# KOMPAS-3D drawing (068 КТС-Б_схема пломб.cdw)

Referenced files: Graphic.tdp
Referenced files in D:\100_Работа\003_КД\003_Проекты\СхемыУстПриборов\: КТС-Б_Труба_Ду100.cdw
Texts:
  ПСПД-0000-2015
  Узел учёта тепловой энергии и теплоносителя
  Кремляков А.И.
  Служба проектно-сметная
  ПромСервисА.И.
  Лит-Масса-Масштаб
  Материал-Предприятие
  Title Specification
  Body Specification ( left align )
  Body Specificaton ( centered )
  ГОСТ 16037-80-У20-ЗН- 3
  пломба
  *Размеры для справок.
  Допустимое   угловое  смещение   деталей поз.1, 2, 3
  относительно фланцев и номинального положения  2 .
  Сварные швы проверить внешним осмотром по ГОСТ 3242-79.
  Трещины, прожоги, свищи, раковины, непровары не допускаются.
  Измерительный участок испытать на прочность и
  герметичность пробным гидравлическим давлением Pпр=2,0 МПа в
  течение 30 мин. Течь, потение, видимые остаточные деформации не
  допускаются.
  Термометр сопротивления поз.1 и выступающие части бобышки
  поз.2 и гильзы поз.3 изолировать на высоту 50...60 мм трубчатой
  теплоизоляцией  1/2"; S=13 мм, закрепив её лентой самоклеещей.
  ООО "ПОИНТ"
  Tермометр
  сопротивления
  платиновый КТС-Б
  Pt100
  Tермометр  сопротивления  платиновый КТС-Б Pt100
  один из
  компл.
  один из компл.
  СДФИ.408727.001-21
  ООО "ПОИНТ" СДФИ.408727.001-21
  Бобышка
  для
  КТС-Б
  для КТС-Б
  Гильза
  ГЦР.105
  Гильза  ГЦР.105
  Поз.
  Кол.
  Приме-
  чание
  Таблица спецификации
  Нач. отд.
  ЗАО "ПромСервис"
  г. Димитровград
  Узел учёта тепловой энергии и
  теплоносителя
  Пломбировка
  термопреобразователя
  ПСПД-0093-2014-
Dimensions and other numbers on the sheet: 1; 2; 3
